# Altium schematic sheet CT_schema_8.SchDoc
size 254 x 194 mm
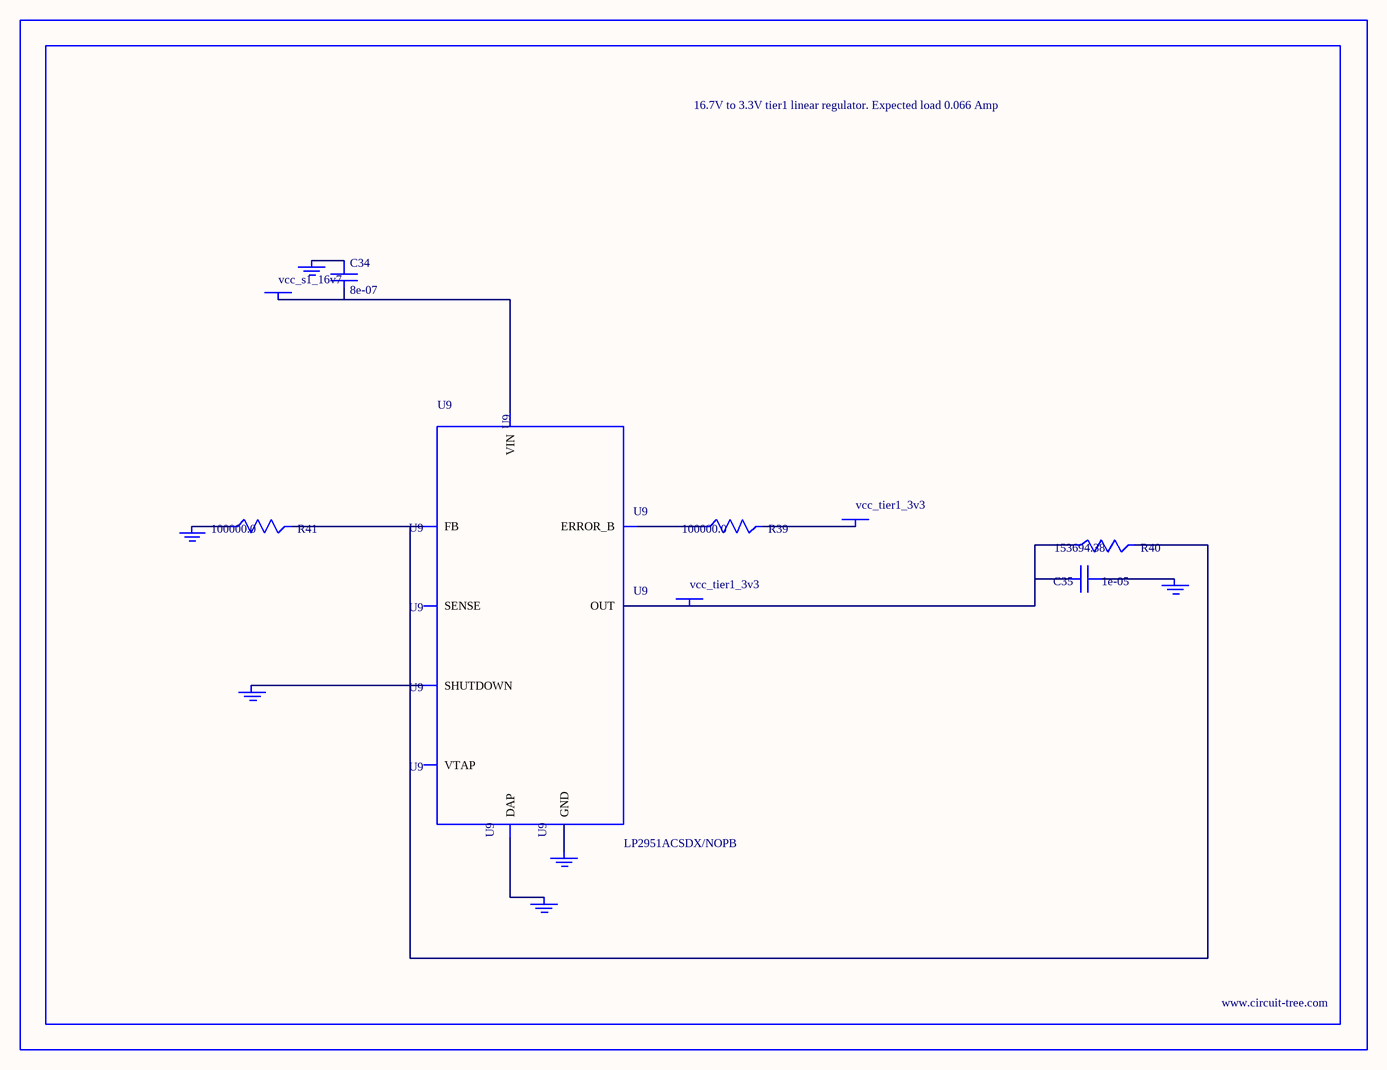
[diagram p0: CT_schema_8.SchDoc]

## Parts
BORDER7  (no value)
C34  8e-07  [R0603]
C35  1e-05  [C1210]
GND_INSTANCE_7_0  (no value)
GND_INSTANCE_7_1  (no value)
GND_INSTANCE_7_2  (no value)
GND_INSTANCE_7_3  (no value)
GND_INSTANCE_7_4  (no value)
GND_INSTANCE_7_5  (no value)
POWER_INSTANCE_7_0  vcc_tier1_3v3
POWER_INSTANCE_7_1  vcc_s1_16v7
POWER_INSTANCE_7_2  vcc_tier1_3v3
R39  100000.0  [R0603]
R40  153694.38  [R0603]
R41  100000.0  [R0603]
U9  LP2951ACSDX/NOPB  [WSON-8]

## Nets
NetC34_1: C34.1 GND_INSTANCE_7_3.0(GND)
NetC34_2: C34.2 POWER_INSTANCE_7_1.0(PWR) U9.8(VIN)
NetC35_1: C35.1 GND_INSTANCE_7_0.0(GND)
NetC35_2: C35.2 POWER_INSTANCE_7_2.0(PWR) R40.1 U9.1(OUT)
NetGND_INSTANCE_7_1_0: GND_INSTANCE_7_1.0(GND) U9.3(SHUTDOWN)
NetGND_INSTANCE_7_2_0: GND_INSTANCE_7_2.0(GND) R41.1
NetGND_INSTANCE_7_4_0: GND_INSTANCE_7_4.0(GND) U9.PAD(DAP)
NetGND_INSTANCE_7_5_0: GND_INSTANCE_7_5.0(GND) U9.4(GND)
NetPOWER_INSTANCE_7_0_0: POWER_INSTANCE_7_0.0(PWR) R39.2
NetR39_1: R39.1 U9.5(ERROR_B)
NetR40_2: R40.2 R41.2 U9.7(FB)

Not connected (* = marked no-connect by the designer): U9 2(SENSE) 6(VTAP)

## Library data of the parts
BORDER7 = BORDER_PAGE7
C34 = C34
C35 = GRM32DR61E106MA12L
GND_INSTANCE_7_0-GND_INSTANCE_7_5 = GND
POWER_INSTANCE_7_0-POWER_INSTANCE_7_2 = PWR
R39 R41 = RC0603JR-07100KL
R40 = R40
